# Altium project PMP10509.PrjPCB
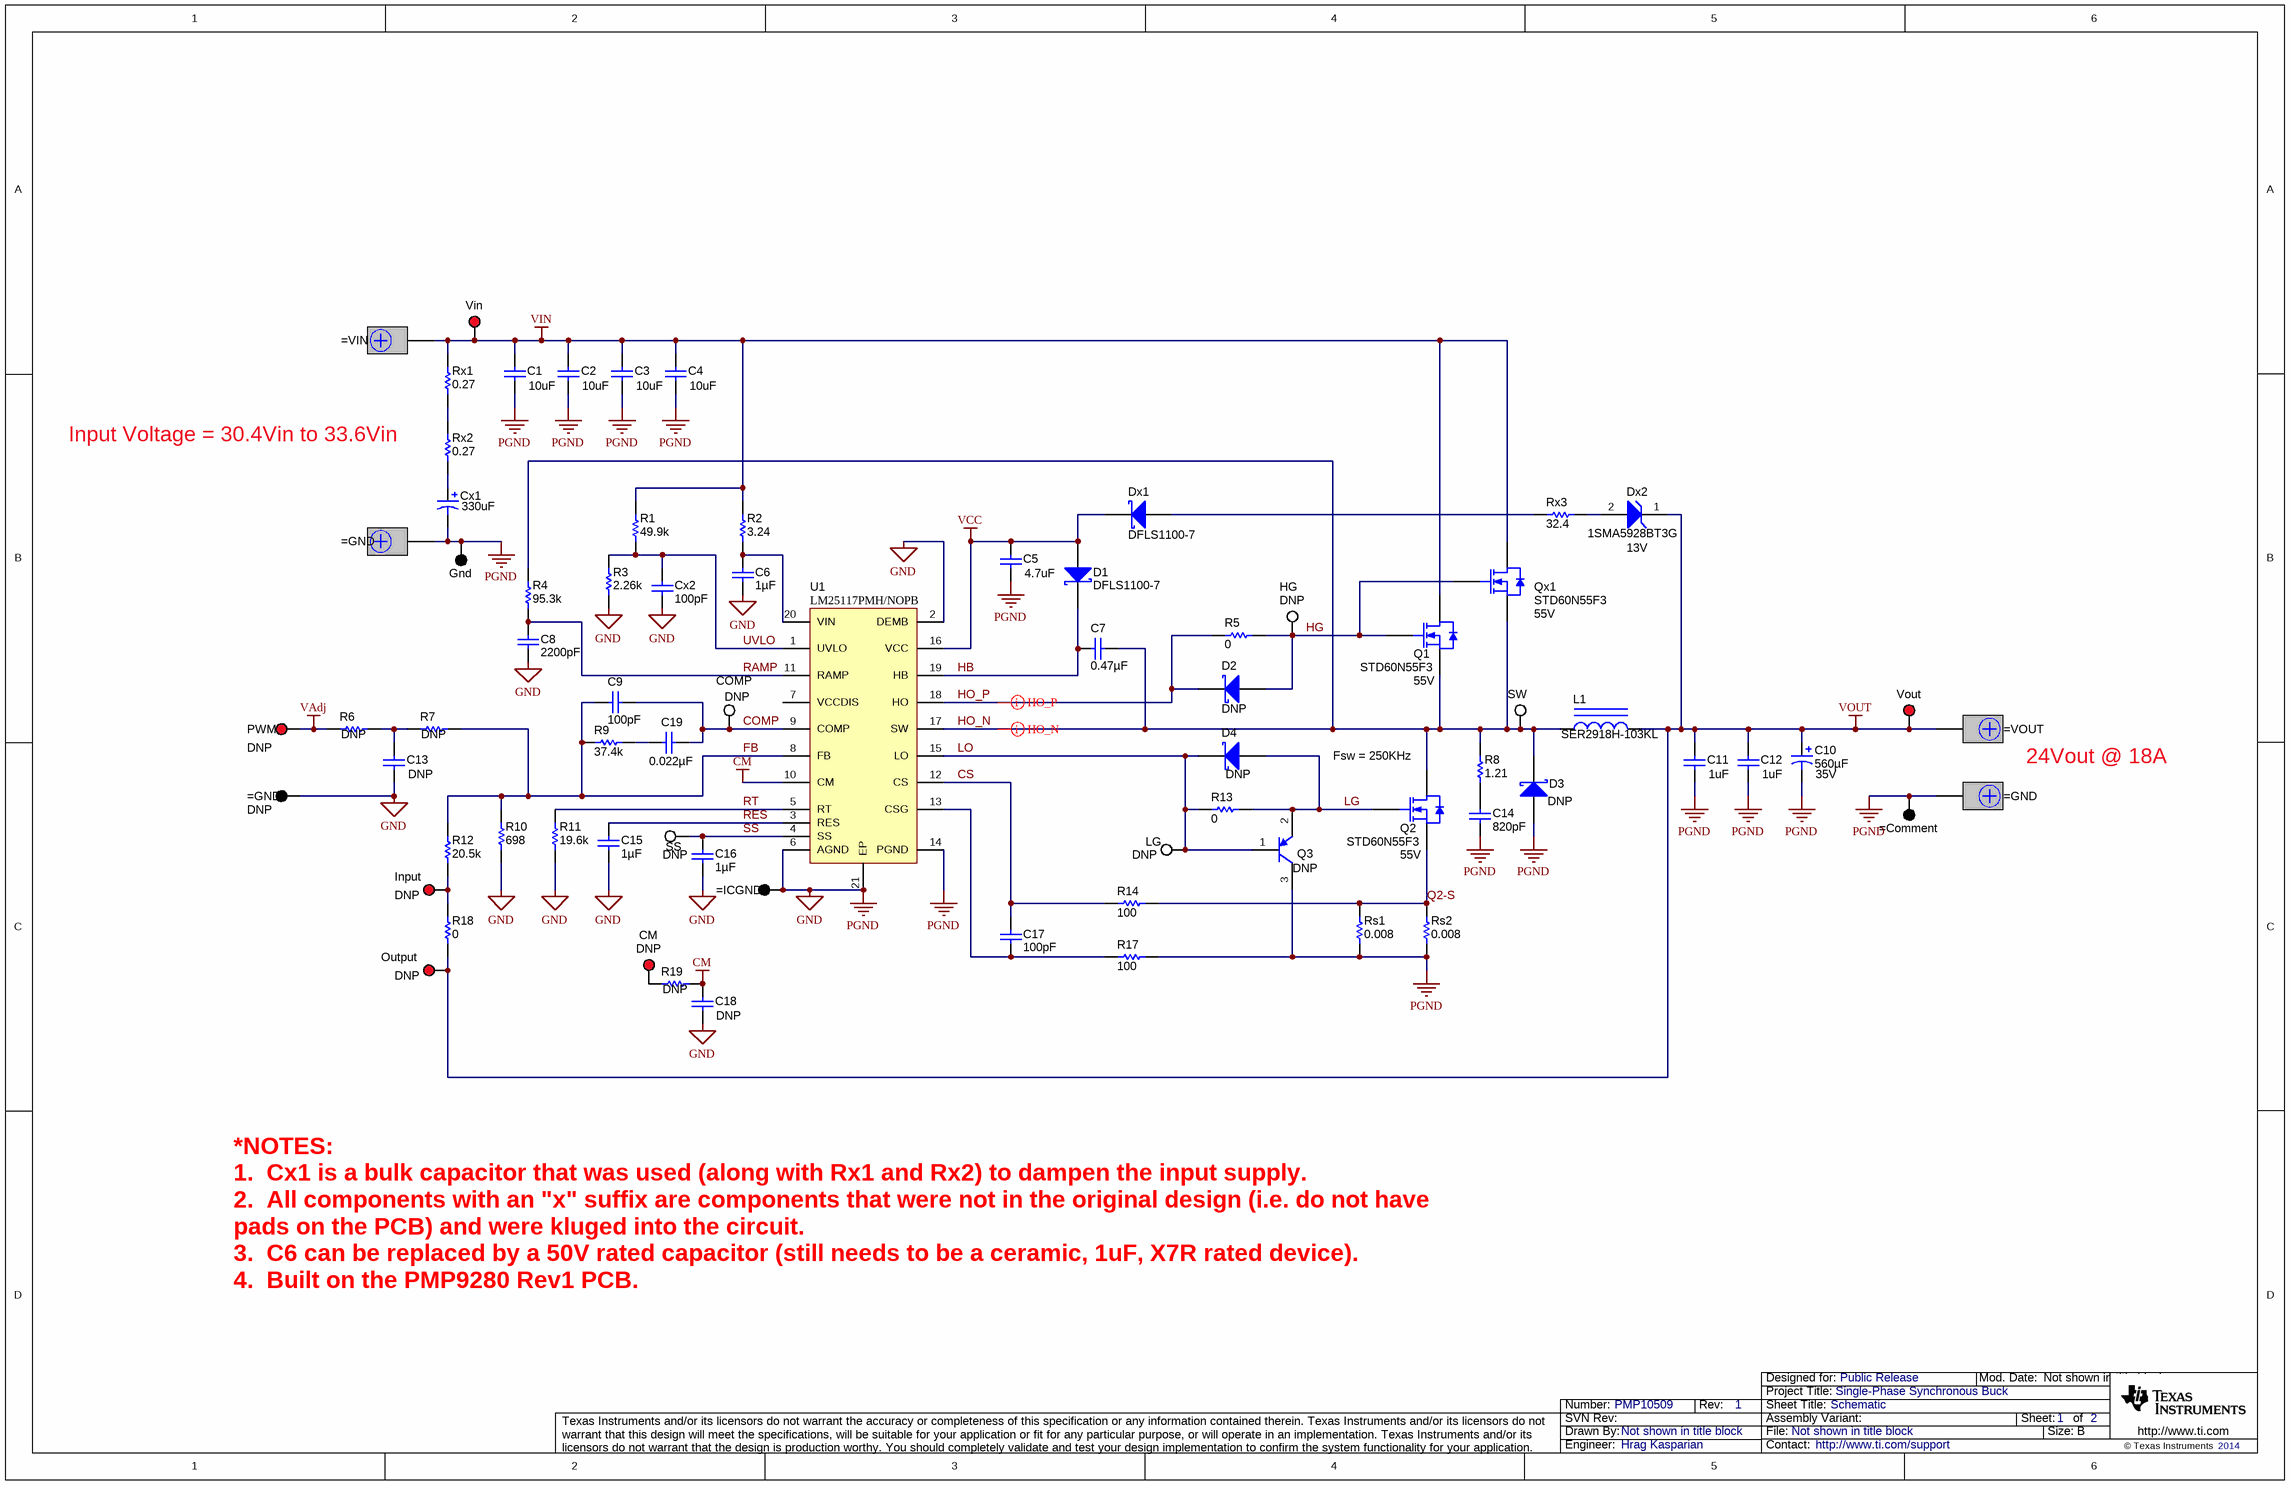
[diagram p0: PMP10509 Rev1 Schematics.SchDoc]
TID: PMP10509; TechSupport: http://www.ti.com/support; SCH_Rev: 1; PRJ_Title: Single-Phase Synchronous Buck; PRJ_Number: PMP10509; PRJ_Engineer: Hrag Kasparian; PRJ_Customer: Public Release; PCB_Rev: 1; PCB_Layout: Unknown; CopyrightYear: 2014
2 sheets, 92 parts. Net scope: global (net labels, ports and power ports of the same name join across sheets).
Board file: PMP9280 Rev 1.PcbDoc
Sheets:
  PMP10509 Rev1 Schematics.SchDoc
  PMP10509_Hardware_ANSI-B.SchDoc

## Sheet PMP10509 Rev1 Schematics.SchDoc: Schematic
size 431 x 279 mm; Date: Not shown in title block; ApprovedBy: Not shown in title block; CheckedBy: Not shown in title block; Author: Not shown in title block; CompanyName: Not shown in title block; DrawnBy: Not shown in title block; Engineer: Not shown in title block; Organization: Not shown in title block; Address1: Not shown in title block; Address2: Not shown in title block; Address3: Not shown in title block; Address4: Not shown in title block; DocumentNumber: 1; Revision: Use project parameter SCH_Rev; SheetNumber: 1; SheetTotal: 2; PageSetup: Record=PageOptions¦CenterHorizontal=True¦CenterVertical=True¦PrintScale=0.62¦XCorrection=1.00¦YCorrection=1.00¦PrintKind=0¦BorderSize=5000000¦LeftOffset=0¦BottomOffset=0¦Orientation=2¦PaperLength=1000¦PaperWidth=1000¦Scale=100¦PaperSource=15¦PrintQuality=600¦MediaType=1¦DitherType=10¦PaperKind=Letter¦PrintScaleMode=1

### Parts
C1  10uF  [TBD]
C2  10uF  [TBD]
C3  10uF  [TBD]
C4  10uF  [TBD]
C5  4.7uF  [TBD]
C6  ValueDisplayed: 1µF  [1206]  (hidden comment: GRM31CR72A105KA01L)
C7  ValueDisplayed: 0.47µF  [0603]  (hidden comment: GRM188R71E474KA12D)
C8  ValueDisplayed: 2200pF  [0603]  (hidden comment: GRM1885C1H222JA01D)
C9  ValueDisplayed: 100pF  [0603L]  (hidden comment: GRM1885C1H101JA01D)
C10  ValueDisplayed: 560µF  Value2: 35V  [CAPPR5-10X20]  (hidden comment: EEU-FR1V681)
C11  1uF  [TBD]
C12  1uF  [TBD]
C13  DNP  [0603L]
C14  ValueDisplayed: 820pF  [0603]  (hidden comment: GRM1885C1H821JA01D)
C15  ValueDisplayed: 1µF  [0603]  (hidden comment: C1608X7R1C105K)
C16  ValueDisplayed: 1µF  [0603]  (hidden comment: C1608X7R1C105K)
C17  ValueDisplayed: 100pF  [0603L]  (hidden comment: GRM1885C1H101JA01D)
C18  DNP  [0603L]
C19  ValueDisplayed: 0.022µF  [0603]  (hidden comment: C0603C223K5RACTU)
CM  DNP  [Keystone5000]
COMP  DNP  [Keystone5002]
Cx1  value 330uF  [TBD]  (hidden comment: 35ME330AX)
Cx2  ValueDisplayed: 100pF  [0603]  (hidden comment: 06035A101FAT2A)
D1  DFLS1100-7  [powerDI123]
D2  DNP  [sod-323]
D3  DNP  [powerDI123]
D4  DNP  [sod-323]
Dx1  DFLS1100-7  [powerDI123]
Dx2  1SMA5928BT3G  value 13V  [TBD]
Gnd  5011  [Keystone5011]  (value not drawn)
Gnd2  (no value)  [Keystone5011]
Gnd3  DNP  [Keystone5011]
Gnd4  ICGND  [Keystone5011]  (value not drawn)
HG  DNP  [Keystone5002]
Input  DNP  [Keystone5000]
J1  (no value)  [CB35-36-CY]
J2  (no value)  [CB35-36-CY]
J3  (no value)  [CB35-36-CY]
J4  (no value)  [CB35-36-CY]
L1  SER2918H-103KL  [SER2918]
LG  DNP  [Keystone5002]
Output  DNP  [Keystone5000]
PWM  DNP  [Keystone5000]
Q1  STD60N55F3  value 55V
Q2  STD60N55F3  value 55V
Q3  DNP  [SOT-23]
Qx1  STD60N55F3  value 55V
R1  value 49.9k  [0603L]  (hidden comment: CRCW060349K9FKEA)
R2  value 3.24  [0603]  (hidden comment: CRCW06033R24FKEA)
R3  value 2.26k  [0603]  (hidden comment: CRCW06032K26FKEA)
R4  value 95.3k  [0603]  (hidden comment: CRCW060395K3FKEA)
R5  value 0  [0603L]  (hidden comment: CRCW06030000Z0EA)
R6  DNP  [0603L]
R7  DNP  [0603L]
R8  value 1.21  [0805_HV]  (hidden comment: CRCW08051R21FKEA)
R9  value 37.4k  [0603]  (hidden comment: CRCW060337K4FKEA)
R10  value 698  [0603]  (hidden comment: CRCW0603698RFKEA)
R11  value 19.6k  [0603]  (hidden comment: CRCW060319K6FKEA)
R12  value 20.5k  [0603]  (hidden comment: CRCW060320K5FKEA)
R13  value 0  [0603L]  (hidden comment: CRCW06030000Z0EA)
R14  value 100  [0603L]  (hidden comment: CRCW0603100RFKEA)
R17  value 100  [0603L]  (hidden comment: CRCW0603100RFKEA)
R18  value 0  [0603L]  (hidden comment: CRCW06030000Z0EA)
R19  DNP  [0603L]
Rs1  value 0.008  [2512M]  (hidden comment: ERJ-M1WSF8M0U)
Rs2  value 0.008  [2512M]  (hidden comment: ERJ-M1WSF8M0U)
Rx1  value 0.27  [1210M]  (hidden comment: MCR25JZHFLR270)
Rx2  value 0.27  [1210M]  (hidden comment: MCR25JZHFLR270)
Rx3  value 32.4  [1206]  (hidden comment: CRCW120632R4FKEA)
SS  DNP  [Keystone5002]
SW  5002  [Keystone5002]  (value not drawn)
U1  LM25117PMH/NOPB  [MXA20A_N]
Vin  5000  [Keystone5000]  (value not drawn)
Vout  Vout 2.2V to 13V@ 15A  [Keystone5000]  (value not drawn)

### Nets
CM: C18.1 R19.1 U1.10(CM)
GND: C1.2 C2.2 C3.2 C4.2 C5.2 C6.2 C8.2 C10.2(-) C11.2 C12.2 C13.2 C14.2 C15.2 C16.2 C18.2 Cx1.2(-) Cx2.2 D3.2(A) Gnd.1 Gnd2.1 Gnd3.1 Gnd4.1 J2.1 J4.1 Q3.3(C) R3.1 R10.1 R11.1 R17.2 Rs1.1 Rs2.1 U1.2(DEMB) U1.6(AGND) U1.14(PGND) U1.21(EP)  [also labelled PGND]
VAdj: PWM.1 R6.1
VCC: C5.1 D1.2(A) Dx1.1(K) U1.16(VCC)
VIN: C1.1 C2.1 C3.1 C4.1 J1.1 Q1.1(D) Qx1.1(D) R1.2 R2.1 Rx1.2 Vin.1
VOUT: C10.1(+) C11.1 C12.1 Dx2.1(K) J3.1 L1.2 Output.1 R18.1 Vout.1
COMP: C9.1 C19.1 COMP.1 U1.9(COMP)
CS: C17.1 R14.1 U1.12(CS)
FB: C9.2 R7.1 R9.1 R10.2 R12.2 U1.8(FB)
HB: C7.1 D1.1(K) U1.19(HB)
HG: D2.2(A) HG.1 Q1.2(G) Qx1.2(G) R5.2
HO_N: C7.2 D3.1(K) L1.1 Q1.3(S) Q2.1(D) Qx1.3(S) R4.2 R8.2 SW.1 U1.17(SW)
HO_P: D2.1(K) R5.1 U1.18(HO)
LG: D4.2(A) Q2.2(G) Q3.2(E) R13.2
LO: D4.1(K) LG.1 Q3.1(B) R13.1 U1.15(LO)
Q2-S: Q2.3(S) R14.2 Rs1.2 Rs2.2
RAMP: C8.1 R4.1 U1.11(RAMP)
RES: C15.1 U1.3(RES)
RT: R11.2 U1.5(RT)
SS: C16.1 SS.1 U1.4(SS)
UVLO: Cx2.1 R1.1 R3.2 U1.1(UVLO)
NetC6_1: C6.1 R2.2 U1.20(VIN)
NetC13_1: C13.1 R6.2 R7.2
NetC14_1: C14.1 R8.1
NetC17_2: C17.2 R17.1 U1.13(CSG)
NetC19_2: C19.2 R9.2
NetCM_1: CM.1 R19.2
NetCx1_1: Cx1.1(+) Rx2.1
NetDx1_2: Dx1.2(A) Rx3.1
NetDx2_2: Dx2.2(A) Rx3.2
NetInput_1: Input.1 R12.1 R18.2
NetRx1_1: Rx1.1 Rx2.2

Not connected (* = marked no-connect by the designer): U1 7(VCCDIS)

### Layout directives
differential pair: HO_N, HO_P

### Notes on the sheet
- Input Voltage = 30.4Vin to 33.6Vin
- (near Q2) Fsw = 250KHz
- 24Vout @ 18A
- *NOTES:
  1.  Cx1 is a bulk capacitor that was used (along with Rx1 and Rx2) to dampen the input supply.
  2.  All components with an "x" suffix are components that were not in the original design (i.e. do not have pads on the PCB) and were kluged into the circuit.
  3.  C6 can be replaced by a 50V rated capacitor (still needs to be a ceramic, 1uF, X7R rated device).
  4.  Built on the PMP9280 Rev1 PCB.

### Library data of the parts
C1-C4 = Capacitor: CAP, CERM, 10uF, 50V, X7R, 10%, 1210; Manufacturer: Samsung Electro Mechanics; PartNumber: CL32B106KBJNNWE; Polarized: N; U/M: EA
C5 = Capacitor: CAP, CERM, 4.7uF, 16V, X7R, 10%, 0805; Manufacturer: Samsung Electro Mechanics; PartNumber: CL21B475KOFNNNE; Polarized: N; U/M: EA
C6 = GRM31CR72A105KA01L: CAP, CERM, 1uF, 100V, +/-10%, X7R, 1206; Manufacturer: MuRata; Polarized: N; CompType: Capacitor; U/M: EA; Cap_F: 0.000001; Tolerance_%: 10; Value1: Unknown; VDC_V: 100; TaMin_C: -55; TaMax_C: 125; Cap_Case: 2220
C7 = GRM188R71E474KA12D: CAP, CERM, 0.47uF, 25V, +/-10%, X7R, 0603; Manufacturer: MuRata; Polarized: N; CompType: Capacitor; U/M: EA; Cap_F: 0.00000047; Tolerance_%: 10; Value1: Unknown; VDC_V: 25; TaMin_C: -55; TaMax_C: 125
C8 = GRM1885C1H222JA01D: CAP, CERM, 2200pF, 50V, +/-5%, C0G/NP0, 0603; Manufacturer: MuRata; Polarized: N; CompType: Capacitor; U/M: EA; Cap_F: 0.0000000022; Tolerance_%: 5; Value1: Unknown; VDC_V: 50; TaMin_C: -55; TaMax_C: 125
C9 C17 = GRM1885C1H101JA01D: CAP, CERM, 100pF, 50V, +/-5%, C0G/NP0, 0603; Manufacturer: MuRata; Polarized: N; CompType: Capacitor; U/M: EA; Cap_F: 0.0000000001; Tolerance_%: 5; Value1: Unknown; VDC_V: 50; TaMin_C: -55; TaMax_C: 125; Cap_Case: 0603
C10 = EEU-FR1V681: CAP, AL, 560uF, 35V, +/-20%, TH; Manufacturer: Panasonic; Polarized: Y; CompType: Capacitor; Value: 680uF; U/M: EA; Cap_F: 0.00068; Tolerance_%: 20; Value1: Unknown; VDC_V: 35; IRMS_A: 2.47; TaMin_C: -40; TaMax_C: 105; Cap_Case: 10x20
C11 C12 = Capacitor: CAP, CERM, 1uF, 25V, X7R, 20%, 0805; Manufacturer: AVX; PartNumber: 08053C105MAT; Polarized: N; U/M: EA
C13 = GRM188R60J106ME47D: CAP, CERM, 10uF, 6.3V, +/-20%, X5R, 0603; Manufacturer: MuRata; Polarized: N; CompType: Capacitor; ValueDisplayed: 10µF; U/M: EA; Cap_F: 0.00001; Tolerance_%: 20; ESR_Ohm: 0.009; Value1: 0.009 ohm; VDC_V: 6.3; IRMS_A: 2.74; TaMin_C: -55; TaMax_C: 125; Cap_Case: 0603
C14 = GRM1885C1H821JA01D: CAP, CERM, 820pF, 50V, +/-5%, C0G/NP0, 0603; Manufacturer: MuRata; Polarized: N; TaMax_C: 125; TaMin_C: -55; Tolerance_%: 5; VDC_V: 50; Cap_F: 0.00000000082; CompType: Capacitor; U/M: EA; Value1: Unknown
C15 C16 = C1608X7R1C105K: CAP, CERM, 1uF, 16V, +/-10%, X7R, 0603; Manufacturer: TDK; Polarized: N; CompType: Capacitor; U/M: EA; Cap_F: 0.000001; Tolerance_%: 10; ESR_Ohm: 0.0057; Value1: 0.0057 ohm; VDC_V: 16; TaMin_C: -55; TaMax_C: 125
C18 = GRM188R61H103KA01D: CAP, CERM, 0.01uF, 50V, +/-10%, X5R, 0603; Manufacturer: MuRata; Polarized: N; CompType: Capacitor; ValueDisplayed: 0.01µF; U/M: EA; Cap_F: 0.00000001; Tolerance_%: 10; Value1: Unknown; VDC_V: 50; TaMin_C: -55; TaMax_C: 85; Cap_Case: 0603
C19 = C0603C223K5RACTU: CAP, CERM, 0.022uF, 50V, +/-10%, X7R, 0603; Manufacturer: Kemet; Polarized: N; CompType: Capacitor; U/M: EA; Cap_F: 0.000000022; Tolerance_%: 10; Value1: Unknown; VDC_V: 50; TaMin_C: -55; TaMax_C: 125
CM Input Output PWM Vin Vout = 5000: Test Point, Miniature, Red, TH; Manufacturer: Keystone; CompType: Test Point Loop; U/M: EA
COMP HG LG SS SW = 5002: Test Point, Miniature, White, TH; Manufacturer: Keystone; CompType: Test Point Loop; U/M: EA
Cx1 = Capacitor_Polarized: CAP, Al Electrolytic, 330F, 35V, +/-20%, 0.044Ohm ESR, TH; Manufacturer: Suncon; Polarized: Y; U/M: EA; Value1: 1.25Arms
Cx2 = 06035A101FAT2A: CAP, CERM, 100pF, 50V, +/-1%, C0G/NP0, 0603; Manufacturer: AVX; Polarized: N; CompType: Capacitor; U/M: EA; Cap_F: 0.0000000001; Tolerance_%: 1; Value1: Unknown; VDC_V: 50; TaMin_C: -55; TaMax_C: 125
D1 D3 Dx1 = DFLS1100-7: Diode, Schottky, 100V, 1A, PowerDI123; Manufacturer: Diodes Inc.; U/M: EA; Vf_V: 0.77; Value2: 0.77V; Io_A: 1; Vr_V: 100; TJmax_C: 175; RJC_CperW: 7
D2 D4 = BAT42WS-7-F: Diode, Schottky, 30V, 0.2A, SOD-323; Manufacturer: Diodes Inc.; U/M: EA; Vf_V: 1; Value2: 1V; Io_A: 0.2; Vr_V: 30
Dx2 = Zener: Diode, Zener, 13V, 1.5W, SMA; Manufacturer: ON Semiconductor; U/M: EA
Gnd Gnd3 Gnd4 = 5011: Test Point, TH, Multipurpose, Black; Manufacturer: Keystone; CompType: Test Point Loop; U/M: EA
Gnd2 = 5011: Test Point, TH, Multipurpose, Black; Manufacturer: Keystone; CompType: Test Point Loop; U/M: EA; Comment_2: GND
J1 = CB35-36-CY: Terminal 50A Lug; Manufacturer: Panduit; SymbolCreator: crossc; CompType: Screw Terminal; U/M: EA
J2 J4 = CB35-36-CY: Terminal 50A Lug; Manufacturer: Panduit; SymbolCreator: crossc; CompType: Screw Terminal; U/M: EA; Comment_1: GND
J3 = CB35-36-CY: Terminal 50A Lug; Manufacturer: Panduit; SymbolCreator: crossc; CompType: Screw Terminal; U/M: EA; Comment_1: VOUT
L1 = SER2918H-103KL: Inductor, Shielded E Core, Ferrite, 10uH, 28A, 0.0026 ohm, SMD; Manufacturer: Coilcraft; ValueDisplayed: 10µH; Ind_H: 10.0E-6; Imax_A: 28; Irms: 28A @ 40C rise; Isat: 32.1A @ 30% inductance drop; DCR_ohm: 0.0026
Q1 Q2 Qx1 = MOSFET_N: MOSFET, N-CH, 55V, 8.5mOhms, DPAK; Manufacturer: ST Microelectronics; U/M: EA; Value1: 0.0085 Ohm
Q3 = MMBT3906, Fairchild Semiconductor: Transistor, PNP, 40V, 0.2A, SOT-23; CompType: BJT; PNP: 1; NPN: 0; Vceo_V: 40; Vcesat1_V: 0.25; Value: 0.25V; IcRated_A: 0.2; HfeMax: 300; TaMin_C: -55; TaMax_C: 150; U/M: EA
R1 = CRCW060349K9FKEA: RES, 49.9k ohm, 1%, 0.1W, 0603; Manufacturer: Vishay-Dale; CompType: Resistor; Res_ohm: 49900; Value_Code: 49k9; Tolerance_%: 1; Power_W: 0.1; VDC_V: 75; TempCo: 100 ppm/C; EIA_Code: E96; U/M: EA
R2 = CRCW06033R24FKEA: RES, 3.24 ohm, 1%, 0.1W, 0603; Manufacturer: Vishay-Dale; CompType: Resistor; Value_Code: 3R24; Tolerance_%: 1; Power_W: 0.1; VDC_V: 75; TempCo: 100 ppm/C; EIA_Code: E96; U/M: EA
R3 = CRCW06032K26FKEA: RES, 2.26k ohm, 1%, 0.1W, 0603; Manufacturer: Vishay-Dale; CompType: Resistor; Res_ohm: 2260; Value_Code: 2k26; Tolerance_%: 1; Power_W: 0.1; VDC_V: 75; TempCo: 100 ppm/C; EIA_Code: E96; U/M: EA
R4 = CRCW060395K3FKEA: RES, 95.3k ohm, 1%, 0.1W, 0603; Manufacturer: Vishay-Dale; CompType: Resistor; Res_ohm: 95300; Value_Code: 95k3; Tolerance_%: 1; Power_W: 0.1; VDC_V: 75; TempCo: 100 ppm/C; EIA_Code: E96; U/M: EA
R5 R13 R18 = CRCW06030000Z0EA: RES, 0 ohm, 5%, 0.1W, 0603; Manufacturer: Vishay-Dale; CompType: Resistor; Value_Code: 0000; Tolerance_%: 5; Power_W: 0.1; VDC_V: 75; TempCo: 200 ppm/C; EIA_Code: E24; U/M: EA
R6 R7 = CRCW06032K00FKEA: RES, 2.00k ohm, 1%, 0.1W, 0603; Manufacturer: Vishay-Dale; CompType: Resistor; Res_ohm: 2000; Value_Code: 2k00; Tolerance_%: 1; Power_W: 0.1; VDC_V: 75; TempCo: 100 ppm/C; EIA_Code: E96; U/M: EA
R8 = CRCW08051R21FKEA: RES, 1.21 ohm, 1%, 0.125W, 0805; Manufacturer: Vishay-Dale; CompType: Resistor; Tolerance_%: 1; VDC_V: 150; Power_W: 0.125; Value_Code: 1R21; EIA_Code: E96; U/M: EA; TempCo: 100 ppm/C
R9 = CRCW060337K4FKEA: RES, 37.4k ohm, 1%, 0.1W, 0603; Manufacturer: Vishay-Dale; CompType: Resistor; Res_ohm: 37400; Value_Code: 37k4; Tolerance_%: 1; Power_W: 0.1; VDC_V: 75; TempCo: 100 ppm/C; EIA_Code: E96; U/M: EA
R10 = CRCW0603698RFKEA: RES, 698 ohm, 1%, 0.1W, 0603; Manufacturer: Vishay-Dale; CompType: Resistor; Value_Code: 698R; Tolerance_%: 1; Power_W: 0.1; VDC_V: 75; TempCo: 100 ppm/C; EIA_Code: E96; U/M: EA
R11 = CRCW060319K6FKEA: RES, 19.6k ohm, 1%, 0.1W, 0603; Manufacturer: Vishay-Dale; CompType: Resistor; Res_ohm: 19600; Value_Code: 19k6; Tolerance_%: 1; Power_W: 0.1; VDC_V: 75; TempCo: 100 ppm/C; EIA_Code: E96; U/M: EA
R12 = CRCW060320K5FKEA: RES, 20.5k ohm, 1%, 0.1W, 0603; Manufacturer: Vishay-Dale; CompType: Resistor; Res_ohm: 20500; Value_Code: 20k5; Tolerance_%: 1; Power_W: 0.1; VDC_V: 75; TempCo: 100 ppm/C; EIA_Code: E96; U/M: EA
R14 R17 = CRCW0603100RFKEA: RES, 100 ohm, 1%, 0.1W, 0603; Manufacturer: Vishay-Dale; CompType: Resistor; Value_Code: 100R; Tolerance_%: 1; Power_W: 0.1; VDC_V: 75; TempCo: 100 ppm/C; EIA_Code: E96; U/M: EA
R19 = CRCW06031K00JNEA: RES, 1.0k ohm, 5%, 0.1W, 0603; Manufacturer: Vishay-Dale; CompType: Resistor; Res_ohm: 1000; Value_Code: 1k00; Tolerance_%: 5; Power_W: 0.1; VDC_V: 75; TempCo: 200 ppm/C; EIA_Code: E24; U/M: EA
Rs1 Rs2 = ERJ-M1WSF8M0U: RES, 0.008 ohm, 1%, 1W, 2512; Manufacturer: Panasonic; CompType: Resistor; Value_Code: R008; Tolerance_%: 1; TempCo: 100 ppm/C; EIA_Code: E96; U/M: EA
Rx1 Rx2 = MCR25JZHFLR270: RES, 0.27 ohm, 1%, 0.5W, 1210; Manufacturer: Rohm; CompType: Resistor; Value_Code: R270; Tolerance_%: 1; Power_W: 0.5; VDC_V: 0; TempCo: 200 ppm/C; EIA_Code: E96; U/M: EA
Rx3 = CRCW120632R4FKEA: RES, 32.4 ohm, 1%, 0.25W, 1206; Manufacturer: Vishay-Dale; CompType: Resistor; Value_Code: 32R4; Tolerance_%: 1; Power_W: 0.25; VDC_V: 200; TempCo: 100 ppm/C; EIA_Code: E96; U/M: EA
U1 = LM5117PMH/NOPB: Wide Vin Range Synchronous Buck Controller, 20-pin TSSOP-EP, Pb-Free; Manufacturer: Texas Instruments; PowerWise: Y; CompType: Switcher; Isolated: No; Buck: Yes; Voltage - Supply: 4.5V ~ 42V; Duty Cycle: 95%; Frequency - Max: 750KHz; Number of Outputs: 1; PWM Type: Current Mode

## Sheet PMP10509_Hardware_ANSI-B.SchDoc: Hardware
size 431 x 279 mm; Date: Not shown in title block; ApprovedBy: Not shown in title block; CheckedBy: Not shown in title block; Author: Not shown in title block; CompanyName: Not shown in title block; Engineer: Not shown in title block; Organization: Not shown in title block; Address1: Not shown in title block; Address2: Not shown in title block; Address3: Not shown in title block; Address4: Not shown in title block; DocumentNumber: 2; Revision: Use project parameter SCH_Rev; SheetNumber: 2; SheetTotal: 2; PageSetup: Record=PageOptions|CenterHorizontal=True|CenterVertical=True|PrintScale=1.00|XCorrection=1.00|YCorrection=1.00|PrintKind=0|BorderSize=5000000|LeftOffset=0|BottomOffset=0|Orientation=2|PaperLength=1000|PaperWidth=1000|Scale=100|PaperSource=15|PrintQuality=600|MediaType=1|DitherType=10|PaperKind=Letter|PrintScaleMode=1
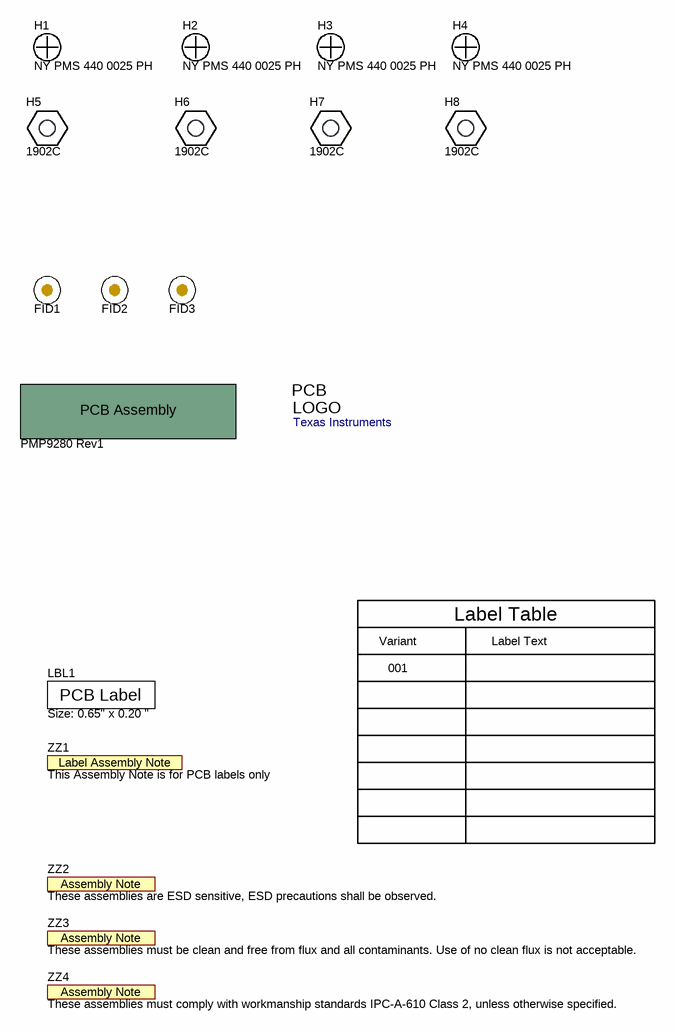
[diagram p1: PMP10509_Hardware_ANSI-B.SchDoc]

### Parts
!PCBA  PMP9280 Rev1  (mechanical)
FID1  Fiducial  [Fiducial10-20]  (value not drawn)
FID2  Fiducial  [Fiducial10-20]  (value not drawn)
FID3  Fiducial  [Fiducial10-20]  (value not drawn)
H1  NY PMS 440 0025 PH  [NY PMS 440 0025 PH]
H2  NY PMS 440 0025 PH  [NY PMS 440 0025 PH]
H3  NY PMS 440 0025 PH  [NY PMS 440 0025 PH]
H4  NY PMS 440 0025 PH  [NY PMS 440 0025 PH]
H5  1902C  [Keystone_1902C]
H6  1902C  [Keystone_1902C]
H7  1902C  [Keystone_1902C]
H8  1902C  [Keystone_1902C]
LBL1  Size: 0.65" x 0.20 "  [Label_650x200]
Logo1  Texas Instruments  [TI_Stacked_SolderMask_Small]  (no BOM)
ZZ1  This Assembly Note is for PCB labels only  [AssemblyNoteLabel]  (no BOM)
ZZ2  These assemblies are ESD sensitive, ESD precautions shall be observed.  [AssemblyNote]  (no BOM)
ZZ3  These assemblies must be clean and free from flux and all contaminants. Use of no clean flux is not acceptable.  [AssemblyNote]  (no BOM)
ZZ4  These assemblies must comply with workmanship standards IPC-A-610 Class 2, unless otherwise specified.  [AssemblyNote]  (no BOM)

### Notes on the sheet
- Variant
- Label Table
- Label Text
- 001

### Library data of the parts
!PCBA = PCBA: PMP9280 Rev1 PCB; SymbolCreator: a0412235
FID1-FID3 = Fiducial: Fiducial mark.  There is nothing to buy or mount.; SymbolCreator: codlsc
H1-H4 = NY PMS 440 0025 PH: Machine Screw, Round, #4-40 x 1/4, Nylon, Philips panhead; Manufacturer: B&F Fastener Supply; CompType: Hardware; SymbolCreator: codlsc; U/M: EA
H5-H8 = 1902C: Standoff, Hex, 0.5"L #4-40 Nylon; Manufacturer: Keystone; CompType: Hardware; SymbolCreator: a0412235
LBL1 = THT-14-423-10: Thermal Transfer Printable Labels, 0.650" W x 0.200" H - 10,000 per roll; Manufacturer: Brady; SymbolCreator: a0412235; CompType: Label
Logo1 = TI_Logo: Texas Instrument Corporate Signature; SymbolCreator: a0412235
ZZ1 = AssemblyNoteLabel: SymbolCreator: a0412235
ZZ2-ZZ4 = AssemblyNote: SymbolCreator: codlsc

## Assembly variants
001: not fitted C13 C18 CM COMP D2 D3 D4 FID1 FID2 FID3 Gnd3 H9 H10 H11 H12 HG Input LG Output PWM Q3 R6 R7 R19 SS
